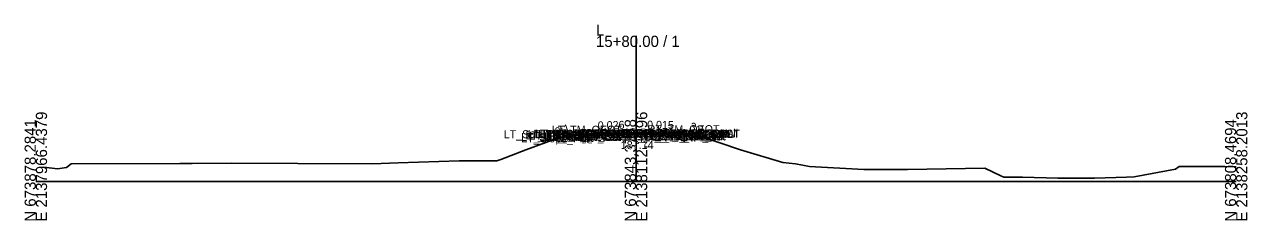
# Model space of a CAD drawing. Extents: x -26 to 5503, y -10 to 7033.
# Drawn here: x 3897.2 to 4202.8, y 490.3 to 539.2 of the extents above; entities that cross this region are included whole.
import ezdxf

# ---------------------------------------------------------------- set-up
doc = ezdxf.new("R2010")
doc.units = 0
for name, color, linetype in [('Default', 7, 'Continuous'), ('Exist CMT Pavement', 7, 'Continuous'), ('Exist Cross Section Cell', 7, 'Continuous'), ('Exist XS Center Line Elevation Label', 7, 'Continuous'), ('Exist XS Ground Line', 7, 'Continuous'), ('Prop CMT Pvmt Course 1', 7, 'Continuous'), ('Prop CMT Pvmt Course 1 Wedge', 7, 'Continuous'), ('Prop CMT Pvmt Course 2', 7, 'Continuous'), ('Prop CMT Pvmt Course 2 Wedge', 7, 'Continuous'), ('Prop CMT Pvmt Course 3', 7, 'Continuous'), ('Prop CMT Pvmt Course 3 Wedge', 7, 'Continuous'), ('Prop CMT Pvmt Surface', 7, 'Continuous'), ('Prop CMT Pvmt Surface Shoulder', 7, 'Continuous'), ('Prop CMT Pvmt Wedge Surface 1', 7, 'Continuous'), ('Prop CMT Pvmt Wedge Surface 2', 7, 'Continuous'), ('Prop CMT Pvmt Wedge Surface 3', 7, 'Continuous'), ('Prop CMT Shld Paved Course 1', 7, 'Continuous'), ('Prop CMT Shld Paved Course 2', 7, 'Continuous'), ('Prop CMT Shld Paved Course 3', 7, 'Continuous'), ('Prop CMT Slope Grass', 7, 'Continuous'), ('Prop CMT Subgrade Earthwork', 7, 'Continuous'), ('Prop XS Earthwork Shape', 7, 'Continuous'), ('Prop XS EOT Tick Mark', 7, 'Continuous'), ('Prop XS SE Text', 7, 'Continuous'), ('Prop XS Side Slope Text', 7, 'Continuous'), ('Prop XS Wedging', 7, 'Continuous')]:
    doc.layers.add(name, color=color, linetype=linetype)

msp = doc.modelspace()

# ---------------------------------------------------------------- linework, layer by layer
at = {"layer": 'Exist CMT Pavement'}
for points in [[(4050, 512.14), (4048.67, 512.12), (4044, 512.04), (4039.33, 511.95), (4038, 511.92)], [(4050, 512.14), (4051.32, 512.12), (4055.96, 512.04), (4060.6, 511.96), (4061.92, 511.93)]]:
    msp.add_lwpolyline(points, dxfattribs=at)
at = {"layer": 'Exist Cross Section Cell'}
for p, q in [((4050, 500), (4050, 536.41)), ((3900, 500), (4050, 500)), ((4050, 500), (4200, 500))]:
    msp.add_line(p, q, dxfattribs=at)
at = {"layer": 'Exist XS Ground Line'}
for p, q in [((4022.47, 507.97), (4029.94, 510.67)), ((4029.94, 510.67), (4032.99, 511.23)), ((4032.99, 511.23), (4037.87, 511.92)), ((4037.87, 511.92), (4042.74, 512.02)), ((4042.74, 512.02), (4049.88, 512.14)), ((4049.88, 512.14), (4054.98, 512.06)), ((4054.98, 512.06), (4061.93, 511.93)), ((4061.93, 511.93), (4064.39, 511.67)), ((4064.39, 511.67), (4065.53, 511.52)), ((4065.53, 511.52), (4076.11, 507.96)), ((4016.22, 505.5), (4022.47, 507.97)), ((4076.11, 507.96), (4086.73, 504.74)), ((3907.7, 503.54), (3908.79, 504.47)), ((3908.79, 504.47), (3936, 504.54)), ((3936, 504.54), (3939.1, 504.55)), ((3939.1, 504.55), (3948.97, 504.58)), ((3948.97, 504.58), (3965.45, 504.54)), ((3965.45, 504.54), (3984.15, 504.48)), ((3984.15, 504.48), (3990.52, 504.67)), ((3990.52, 504.67), (4005.79, 505.18)), ((4005.79, 505.18), (4015.25, 505.21)), ((4015.25, 505.21), (4016.22, 505.5)), ((4086.73, 504.74), (4089.9, 504.48)), ((4089.9, 504.48), (4093.34, 503.74)), ((3901.99, 503.65), (3905.43, 503.17)), ((3905.43, 503.17), (3907.7, 503.54)), ((4093.34, 503.74), (4106.95, 503.06)), ((4106.95, 503.06), (4117.85, 503.04)), ((4117.85, 503.04), (4137.2, 503.4)), ((4137.2, 503.4), (4141.19, 501.43)), ((4141.19, 501.43), (4141.92, 501.13)), ((4174.48, 501.23), (4184.81, 503.14)), ((4184.81, 503.14), (4185.78, 503.74)), ((4185.78, 503.74), (4197.18, 503.76)), ((4197.18, 503.76), (4200, 503.69)), ((4141.92, 501.13), (4142.51, 501.12)), ((4142.51, 501.12), (4146.63, 501.12)), ((4146.63, 501.12), (4155.46, 500.89)), ((4155.46, 500.89), (4164.59, 500.86)), ((4164.59, 500.86), (4172.6, 501.09)), ((4172.6, 501.09), (4174.48, 501.23))]:
    msp.add_line(p, q, dxfattribs=at)
at = {"layer": 'Prop CMT Pvmt Course 1'}
for points in [[(4050, 512.26), (4038, 511.96)], [(4038, 511.83), (4050, 512.14)], [(4038, 511.96), (4038, 511.71), (4038, 511.71), (4038, 511.83)], [(4050, 512.14), (4050, 512.26)], [(4050, 512.26), (4062, 512.09)], [(4050, 512.14), (4050, 512.26)], [(4061.92, 511.97), (4050, 512.14)], [(4061.92, 511.84), (4061.92, 511.97)], [(4062, 511.84), (4061.92, 511.84)], [(4062, 512.09), (4062, 511.84)]]:
    msp.add_lwpolyline(points, dxfattribs=at)
at = {"layer": 'Prop CMT Pvmt Course 1 Wedge'}
for points in [[(4050, 512.14), (4038, 511.83)], [(4050, 512.14), (4061.92, 511.97)]]:
    msp.add_lwpolyline(points, dxfattribs=at)
at = {"layer": 'Prop CMT Pvmt Course 2'}
for points in [[(4061.92, 511.63), (4061.92, 511.84)], [(4061.92, 511.84), (4062, 511.84)], [(4062, 511.63), (4061.92, 511.63)], [(4062, 511.84), (4062, 511.63)]]:
    msp.add_lwpolyline(points, dxfattribs=at)
at = {"layer": 'Prop CMT Pvmt Course 2 Wedge'}
for points in [[(4050, 512.01), (4038, 511.71)], [(4050, 512.01), (4061.92, 511.84)]]:
    msp.add_lwpolyline(points, dxfattribs=at)
at = {"layer": 'Prop CMT Pvmt Course 3'}
for points in [[(4038, 511.5), (4038, 511.5), (4038, 511.16), (4038, 511.16)], [(4038, 511.16), (4038, 511.5)], [(4061.92, 511.63), (4062, 511.63)], [(4061.92, 511.3), (4061.92, 511.63)], [(4062, 511.3), (4061.92, 511.3)], [(4062, 511.63), (4062, 511.3)]]:
    msp.add_lwpolyline(points, dxfattribs=at)
at = {"layer": 'Prop CMT Pvmt Course 3 Wedge'}
for points in [[(4050, 511.81), (4038, 511.5)], [(4050, 511.81), (4061.92, 511.63)]]:
    msp.add_lwpolyline(points, dxfattribs=at)
at = {"layer": 'Prop CMT Pvmt Surface'}
for points in [[(4050, 512.26), (4038, 511.96)], [(4050, 512.26), (4062, 512.09)]]:
    msp.add_lwpolyline(points, dxfattribs=at)
at = {"layer": 'Prop CMT Pvmt Surface Shoulder'}
for points in [[(4038, 511.96), (4037.87, 511.95)], [(4062, 512.09), (4062, 512.09)]]:
    msp.add_lwpolyline(points, dxfattribs=at)
at = {"layer": 'Prop CMT Pvmt Wedge Surface 1'}
for points in [[(4050, 512.14), (4038, 511.83)], [(4038, 511.83), (4038, 511.96)], [(4038, 511.96), (4038, 511.96)], [(4050, 512.14), (4061.92, 511.97)], [(4061.92, 511.97), (4061.92, 512.09)], [(4061.92, 512.09), (4062, 512.09)]]:
    msp.add_lwpolyline(points, dxfattribs=at)
at = {"layer": 'Prop CMT Pvmt Wedge Surface 2'}
for points in [[(4050, 512.01), (4038, 511.71)], [(4038, 511.71), (4038, 511.96)], [(4038, 511.71), (4038, 511.71)], [(4050, 512.01), (4061.92, 511.84), (4062, 511.84)], [(4062, 511.84), (4062, 512.09)]]:
    msp.add_lwpolyline(points, dxfattribs=at)
at = {"layer": 'Prop CMT Pvmt Wedge Surface 3'}
for points in [[(4038, 511.5), (4038, 511.96)], [(4050, 511.81), (4038, 511.5)], [(4038, 511.5), (4038, 511.5)], [(4050, 511.81), (4061.92, 511.63), (4062, 511.63)], [(4062, 511.63), (4062, 512.09)]]:
    msp.add_lwpolyline(points, dxfattribs=at)
at = {"layer": 'Prop CMT Shld Paved Course 1'}
for points in [[(4038, 511.96), (4037.87, 511.95), (4037.61, 511.7)], [(4037.61, 511.7), (4038, 511.71)], [(4038, 511.71), (4038, 511.96)], [(4062, 512.09), (4062, 512.09)], [(4062, 512.09), (4062.26, 511.83)], [(4062, 511.84), (4062, 512.09)], [(4062.26, 511.83), (4062, 511.84)]]:
    msp.add_lwpolyline(points, dxfattribs=at)
at = {"layer": 'Prop CMT Shld Paved Course 2'}
for points in [[(4038, 511.71), (4037.61, 511.7), (4037.4, 511.48)], [(4037.4, 511.48), (4038, 511.5)], [(4038, 511.5), (4038, 511.71)], [(4062, 511.84), (4062.26, 511.83), (4062.47, 511.62)], [(4062, 511.63), (4062, 511.84)], [(4062.47, 511.62), (4062, 511.63)]]:
    msp.add_lwpolyline(points, dxfattribs=at)
at = {"layer": 'Prop CMT Shld Paved Course 3'}
for points in [[(4037.4, 511.48), (4037.06, 511.14)], [(4037.06, 511.14), (4038, 511.16)], [(4038, 511.5), (4037.4, 511.48)], [(4037.4, 511.48), (4037.4, 511.48)], [(4038, 511.16), (4038, 511.5)], [(4062, 511.63), (4062.47, 511.62)], [(4062, 511.3), (4062, 511.63)], [(4062.81, 511.28), (4062, 511.3)], [(4062.47, 511.62), (4062.47, 511.62)], [(4062.47, 511.62), (4062.81, 511.28)]]:
    msp.add_lwpolyline(points, dxfattribs=at)
at = {"layer": 'Prop CMT Slope Grass'}
for points in [[(4033, 511.56), (4030.8, 510.83)], [(4037.87, 511.95), (4033, 511.56)], [(4062, 512.09), (4064, 511.93)], [(4064, 511.93), (4065.03, 511.59)]]:
    msp.add_lwpolyline(points, dxfattribs=at)
at = {"layer": 'Prop CMT Subgrade Earthwork'}
for points in [[(4037.06, 511.14), (4036.37, 511.83)], [(4038, 511.16), (4037.06, 511.14)], [(4038, 511.16), (4038, 511.92)], [(4038, 511.16), (4038, 511.16)], [(4061.92, 511.3), (4061.92, 511.93)], [(4061.92, 511.3), (4062, 511.3)], [(4062, 511.3), (4062.81, 511.28)], [(4062.81, 511.28), (4063.5, 511.97)]]:
    msp.add_lwpolyline(points, dxfattribs=at)
at = {"layer": 'Prop XS Earthwork Shape'}
for points in [[(4036.46, 511.74), (4036.37, 511.83), (4033, 511.56), (4030.8, 510.83), (4032.99, 511.23)], [(4036.46, 511.74), (4037.87, 511.95), (4038, 511.92), (4038, 511.16), (4037.06, 511.14)], [(4039.33, 511.95), (4042.74, 512.02), (4044, 512.04)], [(4048.67, 512.12), (4049.88, 512.14), (4050, 512.14)], [(4061.92, 511.93), (4063.31, 511.79), (4062.81, 511.28), (4062, 511.3), (4061.92, 511.3)], [(4063.31, 511.79), (4064.39, 511.67), (4065.03, 511.59), (4064, 511.93), (4063.5, 511.97)]]:
    msp.add_lwpolyline(points, close=True, dxfattribs=at)
at = {"layer": 'Prop XS EOT Tick Mark'}
for points in [[(4038, 511.96), (4038, 512.96)], [(4038, 511.96), (4038, 512.96)], [(4038, 511.96), (4038, 512.96)], [(4062, 512.09), (4062, 513.09)], [(4062, 512.09), (4062, 513.09)], [(4062, 512.09), (4062, 513.09)]]:
    msp.add_lwpolyline(points, dxfattribs=at)
at = {"layer": 'Prop XS Wedging'}
for p, q in [((4038, 512.96), (4038, 509.8)), ((4062, 513.09), (4062, 509.8))]:
    msp.add_line(p, q, dxfattribs=at)

# ---------------------------------------------------------------- texts
at = {"layer": 'Default'}
for s, height, p in [('LT_TM_OEOT', 2, (4028.94, 511.96)), ('RT_TM_OEOT', 2, (4052.9, 512.09)), ('LT_Sub_Trench_Out_DLT', 2, (4016.93, 510.83)), ('LT_Sub_Trench_Out', 2, (4021.26, 510.14)), ('LT_Slope_Fill', 2, (4021.32, 509.83)), ('LT_GS_OS_CTL', 2, (4022.37, 510.56)), ('LT_PV_Sub_Tie_Out', 2, (4022.95, 510.92)), ('LT_PS3_Shelf_Out', 2, (4023.38, 510.48)), ('LT_PV1_OEEOP_Null', 2, (4024.46, 510.96)), ('LT_PV_EG_TestPt3', 2, (4024.85, 510.95)), ('LT_PV_OEEOP_EG', 2, (4025.54, 510.92)), ('LT_PV1_OEEOP_W', 2, (4025.98, 510.83)), ('LT_Sub_OEEOP', 2, (4027.21, 510.16)), ('LT_PV2_OEEOP', 2, (4027.31, 510.71)), ('LT_PV3_OEEOP', 2, (4027.31, 510.5)), ('LT_PS3_OEOP', 2, (4027.64, 510.48)), ('LT_PS2_OEOP', 2, (4027.85, 510.7)), ('LT_Sub_OEOT', 2, (4028.08, 510.16)), ('LT_PV2_OEOT', 2, (4028.17, 510.71)), ('LT_PV3_OEOT', 2, (4028.17, 510.5)), ('LT_PS1_OEOP', 2, (4028.67, 510.95)), ('LT_PV1_OEOT', 2, (4028.74, 510.96)), ('LT_PV_EG_TestPt2', 2, (4029.51, 511.04)), ('LT_PV_EG_TestPt1', 2, (4034.75, 511.12)), ('RT_PV_EG_TestPt1', 2, (4037.35, 511.12)), ('PV_EPGL_EG', 2, (4041.24, 511.14)), ('RT_PV_EG_TestPt2', 2, (4041.43, 511.04)), ('PV2_PGL_W', 2, (4042.02, 511.01)), ('PV3_PGL_W', 2, (4042.02, 510.81)), ('PV1_PGL_W', 2, (4042.58, 511.14)), ('RT_Sub_Trench_Out_DLT', 2, (4044.01, 510.97)), ('PV1_PGL', 2, (4044.47, 511.26)), ('RT_PV_EG_TestPt3', 2, (4046.06, 510.96)), ('RT_PV_Sub_Tie_Out', 2, (4046.82, 510.93)), ('RT_Sub_Trench_Out', 2, (4046.96, 510.28)), ('RT_PV1_OEEOP_Null', 2, (4048.33, 511.09)), ('RT_PS3_Shelf_Out', 2, (4048.4, 510.62)), ('RT_PV_OEEOP_EG', 2, (4049.42, 510.93)), ('RT_PV1_OEEOP_W', 2, (4049.86, 510.97)), ('RT_Sub_OEEOP', 2, (4051.09, 510.3)), ('RT_PV2_OEEOP', 2, (4051.18, 510.84)), ('RT_PV3_OEEOP', 2, (4051.18, 510.63)), ('RT_Sub_OEOT', 2, (4052.03, 510.3)), ('RT_PV2_OEOT', 2, (4052.13, 510.84)), ('RT_PV3_OEOT', 2, (4052.13, 510.63)), ('RT_PS2_OEOP', 2, (4052.44, 510.83)), ('RT_PS3_OEOP', 2, (4052.66, 510.62)), ('RT_PV1_OEOT', 2, (4052.69, 511.09)), ('RT_PS1_OEOP', 2, (4052.76, 511.09)), ('RT_GS_OS_CTL', 2, (4053.32, 510.93)), ('RT_Slope_Fill', 2, (4055.5, 510.59)), ('-', 0.0001, (3900, 500))]:
    msp.add_text(s, height=height, dxfattribs=at).set_placement(p)
at = {"layer": 'Exist Cross Section Cell'}
for s, p in [('L', (4040, 536.41)), ('15+80.00 / 1', (4040, 533.61))]:
    msp.add_text(s, height=2.8, dxfattribs=at).set_placement(p)
for s, p in [('E 2137966.4379', (3902.8, 490)), ('E 2138112.3196', (4052.8, 490)), ('E 2138258.2013', (4202.8, 490)), ('N 673878.2841', (3900, 490)), ('N 673843.3768', (4050, 490)), ('N 673808.4694', (4200, 490))]:
    msp.add_text(s, height=2.8, rotation=90, dxfattribs=at).set_placement(p)
at = {"layer": 'Exist XS Center Line Elevation Label'}
msp.add_text('187.14', height=2, dxfattribs=at).set_placement((4046.2, 508.14))
at = {"layer": 'Prop XS SE Text'}
for s, rotation, p in [('0.026', 1.4797, (4040.46, 513.02)), ('0.015', 359.1608, (4052.76, 513.22))]:
    msp.add_text(s, height=2, rotation=rotation, dxfattribs=at).set_placement(p)
at = {"layer": 'Prop XS Side Slope Text'}
for rotation, p in [(18.4349, (4030.15, 511.4)), (341.5651, (4063.23, 512.98))]:
    msp.add_text('3:1', height=2, rotation=rotation, dxfattribs=at).set_placement(p)

doc.saveas('drawing.dxf')
